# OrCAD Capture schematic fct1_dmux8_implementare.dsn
size A
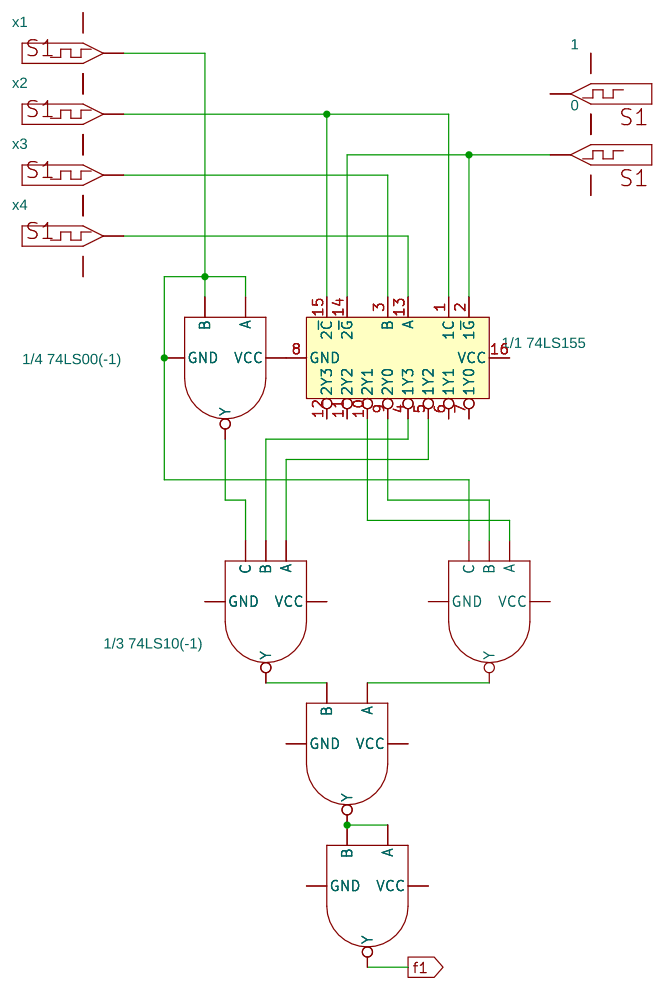
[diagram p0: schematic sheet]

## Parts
0  DigStim1
1  DigStim1
U1  1/1 74LS155  [DIP.100/16/W.300/L.900]
U2  1/4 74LS00(-1)  [DIP.100/14/W.300/L.800]  (section A)
U3  1/3 74LS10(-1)  [DIP.100/14/W.300/L.800]  (sections A,B)
U5  7400  [DIP.100/14/W.300/L.800]  (sections A,B)
x1  DigStim1
x2  DigStim1
x3  DigStim1
x4  DigStim1

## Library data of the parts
0 1 x1-x4 = DigStim1
U1 = 74LS155A
U2 = 74LS00
U3 = 74LS10
U5 = 7400

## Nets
GND: 0.3(GND) 1.3(GND) U1.8(GND) U2.7(GND) U3.7(GND) U5.7(GND) x1.3(GND) x2.3(GND) x3.3(GND) x4.3(GND)
VCC: 0.2(VCC) 1.2(VCC) U1.16(VCC) U2.14(VCC) U3.14(VCC) U5.14(VCC) x1.2(VCC) x2.2(VCC) x3.2(VCC) x4.2(VCC)
f1: U5.6(Y)
N14805: U2.1(A) U2.2(B) U3.5(C) x1.OUT
N14904: U1.13(A) x4.OUT
N14911: U1.3(B) x3.OUT
N14924: U1.1(1C) U1.15(2~{C}) x2.OUT
N14956: 0.OUT U1.2(1~{G}) U1.14(2~{G})
N15374: U3.12(Y) U5.2(B)
N15384: U3.6(Y) U5.1(A)
N15610: U2.3(Y) U3.13(C)
N16375: U1.5(1Y2) U3.1(A)
N16387: U1.4(1Y3) U3.2(B)
N16415: U1.9(2Y0) U3.4(B)
N16458: U1.10(2Y1) U3.3(A)
N16593: U5.3(Y) U5.4(A) U5.5(B)

Not connected (* = marked no-connect by the designer): 1 OUT; U1 6(1Y1) 7(1Y0) 11(2Y2) 12(2Y3)
